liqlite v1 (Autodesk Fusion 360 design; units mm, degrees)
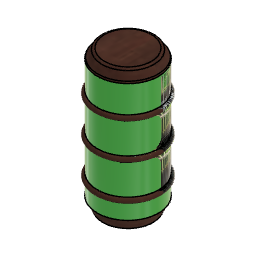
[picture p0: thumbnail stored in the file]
sketch "Sketch1" plane through (0, 0, 0) normal (0, 1, 0) x axis (1, 0, 0)
  line L1 (-30, -70) -> (0, -70)
  line L2 (0, 47.2583) -> (-30, 47.2583)
  line L3 (0, 57.9583) -> (0, 47.2583)
  line L4 (-24.5208, 57.9583) -> (0, 57.9583)
  line L5 (-30, 47.2583) -> (-24.5208, 57.9583)
  line L6 (-24.5208, -78.2437) -> (-30, -70)
  line L7 (0, -78.2437) -> (-24.5208, -78.2437)
  line L8 (0, -70) -> (0, -78.2437)
  line L9 (-30, -42.5) -> (-30, -70)
  line L10 (-30, -7.5) -> (-30, -37.5)
  line L11 (-30, 27.5) -> (-30, -2.5)
  line L12 (-30, 47.2583) -> (-30, 32.5)
  line L13 (-12.2604, -7.5) -> (-15, -7.5)
  line L14 (0, -7.5) -> (0, -70)
  line L15 (0, 47.2583) -> (0, 27.5)
  line L16 (0, 47.2583) -> (0, -7.5)
  arc A1 centre (-30, -40) radius 2.5 clockwise from (-30, -42.5) to (-30, -37.5)
  arc A2 centre (-30, -5) radius 2.5 clockwise from (-30, -7.5) to (-30, -2.5)
  arc A3 centre (-30, 30) radius 2.5 clockwise from (-30, 27.5) to (-30, 32.5)
  point P10 (-30, -40)
  point P20 (0, 27.5)
  horizontal L1
  perpendicular L1 L9
  perpendicular L2 L9
  perpendicular L2 L3
  perpendicular L3 L4
  perpendicular L7 L9
  perpendicular L1 L8
  perpendicular L2 L14
  coincident P10 L9
  collinear L9 L10
  collinear L10 L11
  collinear L11 L12
  tangent A2 L13
  coincident P20 L14
  collinear L14 L15
  dimension "d2" diameter A1 = 5
  dimension "d5" R-Pattern1-uDistance = 0
  dimension "d6" R-Pattern1-vDistance = 70
revolve "Revolve1" sketch "Sketch1" AlongAngle 360
fillet "Fillet1" radius 3
fillet "Fillet2" radius 3
decal "Decal1"
decal "Decal2"
decal "Decal3"
extrude "Extrude1" cut sketch "Sketch1" profile of L1 L15 A2 A3 L13 along normal blind 5
extrude "Extrude2" cut sketch "Sketch1" profile of L1 L13 along normal blind 5
extrude "Extrude3" cut sketch "Sketch1" profile of L1 L13 along normal blind 50
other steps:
create_component "CreateComponent1"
